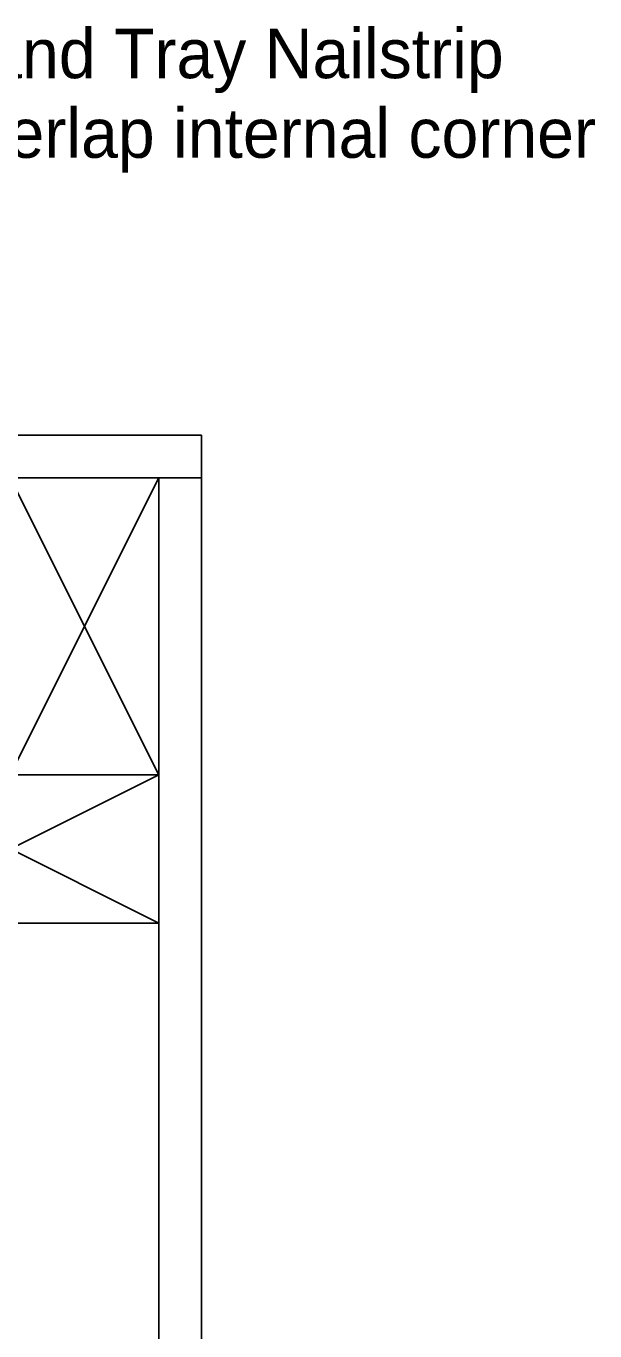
# Model space of a CAD drawing. Extents: x -2.36 to 6.66, y -3.72 to 4.13.
# Drawn here: x 2.2301 to 2.4026, y -2.2717 to -1.876 of the extents above; entities that cross this region are included whole.
import ezdxf

# ---------------------------------------------------------------- set-up
doc = ezdxf.new("R2010")
doc.units = 0
for name, color, linetype in [('A-____-____-IDEN', 7, 'Continuous'), ('A-DETL-____-MEDM', 7, 'Continuous'), ('A-DETL-GENF-OTLN', 7, 'Continuous'), ('A-WALL-____-MCUT', 7, 'Continuous'), ('A-WALL-____-PATT', 7, 'Continuous'), ('A-WALL-FNSH-MCUT', 7, 'Continuous')]:
    doc.layers.add(name, color=color, linetype=linetype)

# ---------------------------------------------------------------- blocks, each defined once
blk = doc.blocks.new('DET_ST_Framing Detail Timber - 45x90-Detail Flashings - Hiland Nailstrip Corner')
at = {"layer": 'A-DETL-____-MEDM'}
for p, q in [((0.09000000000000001, 0.045000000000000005), (0, 0.045000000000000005)), ((0.09000000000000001, 0), (0.09000000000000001, 0.045000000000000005)), ((0, 0), (0.09000000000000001, 0))]:
    blk.add_line(p, q, dxfattribs=at)
at = {"layer": 'A-DETL-GENF-OTLN'}
for p, q in [((0, 0.04500000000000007), (0.09000000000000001, 0)), ((0.09000000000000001, 0.045000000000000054), (0, 0))]:
    blk.add_line(p, q, dxfattribs=at)
blk = doc.blocks.new('DET_ST_Framing Detail Timber - 45x90-V12-Detail Flashings - Hiland Nailstrip Corner')
at = {"layer": 'A-DETL-____-MEDM'}
for p, q in [((0.09000000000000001, 0.045000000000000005), (0, 0.045000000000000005)), ((0, 0.045000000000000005), (0, 0)), ((0.09000000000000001, 0), (0.09000000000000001, 0.045000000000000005)), ((0, 0), (0.09000000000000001, 0))]:
    blk.add_line(p, q, dxfattribs=at)
at = {"layer": 'A-DETL-GENF-OTLN'}
for p, q in [((0, 0.04500000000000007), (0.09000000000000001, 0)), ((0.09000000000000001, 0.045000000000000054), (0, 0))]:
    blk.add_line(p, q, dxfattribs=at)

msp = doc.modelspace()

# ---------------------------------------------------------------- linework, layer by layer
at = {"layer": 'A-WALL-____-MCUT'}
msp.add_line((2.270342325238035, -2.148000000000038), (2.270342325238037, -2.7000000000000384), dxfattribs=at)
at = {"layer": 'A-WALL-____-PATT'}
for p, q in [((2.283342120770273, -2.000000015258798), (1.9236373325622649, -2.000000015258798)), ((2.283342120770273, -2.0129999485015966), (2.283342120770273, -2.000000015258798)), ((1.9236373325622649, -2.0129999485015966), (2.2703417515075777, -2.0129999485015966)), ((2.2703417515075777, -2.0129999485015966), (2.270342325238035, -2.0129999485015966)), ((2.270342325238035, -2.0129999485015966), (2.283342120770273, -2.0129999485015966)), ((2.283342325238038, -2.013000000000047), (2.2703423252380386, -2.013000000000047)), ((2.2703423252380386, -2.013000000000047), (2.27034232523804, -2.70000000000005)), ((2.2833423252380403, -2.70000000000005), (2.283342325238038, -2.013000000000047)), ((2.2703423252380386, -2.148000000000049), (2.180342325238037, -2.148000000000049)), ((2.27034232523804, -2.70000000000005), (2.2703423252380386, -2.148000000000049))]:
    msp.add_line(p, q, dxfattribs=at)
at = {"layer": 'A-WALL-FNSH-MCUT'}
for p, q in [((2.283342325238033, -2.0000000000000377), (1.9236371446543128, -2.0000000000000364)), ((2.283342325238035, -2.7000000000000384), (2.283342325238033, -2.0000000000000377))]:
    msp.add_line(p, q, dxfattribs=at)

# ---------------------------------------------------------------- block references
at = {"layer": 'A-DETL-GENF-OTLN'}
for name, rotation in [('DET_ST_Framing Detail Timber - 45x90-Detail Flashings - Hiland Nailstrip Corner', 89.9999999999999), ('DET_ST_Framing Detail Timber - 45x90-V12-Detail Flashings - Hiland Nailstrip Corner', 180)]:
    msp.add_blockref(name, (2.2703423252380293, -2.103000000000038), dxfattribs=dict(at, rotation=rotation))

# ---------------------------------------------------------------- texts
at = {"layer": 'A-____-____-IDEN'}
for s, p in [('Stratco Hiland Tray Nailstrip', (2.125227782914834, -1.8917513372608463)), ('double underlap internal corner', (2.125227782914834, -1.915894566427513))]:
    msp.add_text(s, height=0.014999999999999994, dxfattribs=at).set_placement(p)

doc.saveas('drawing.dxf')
